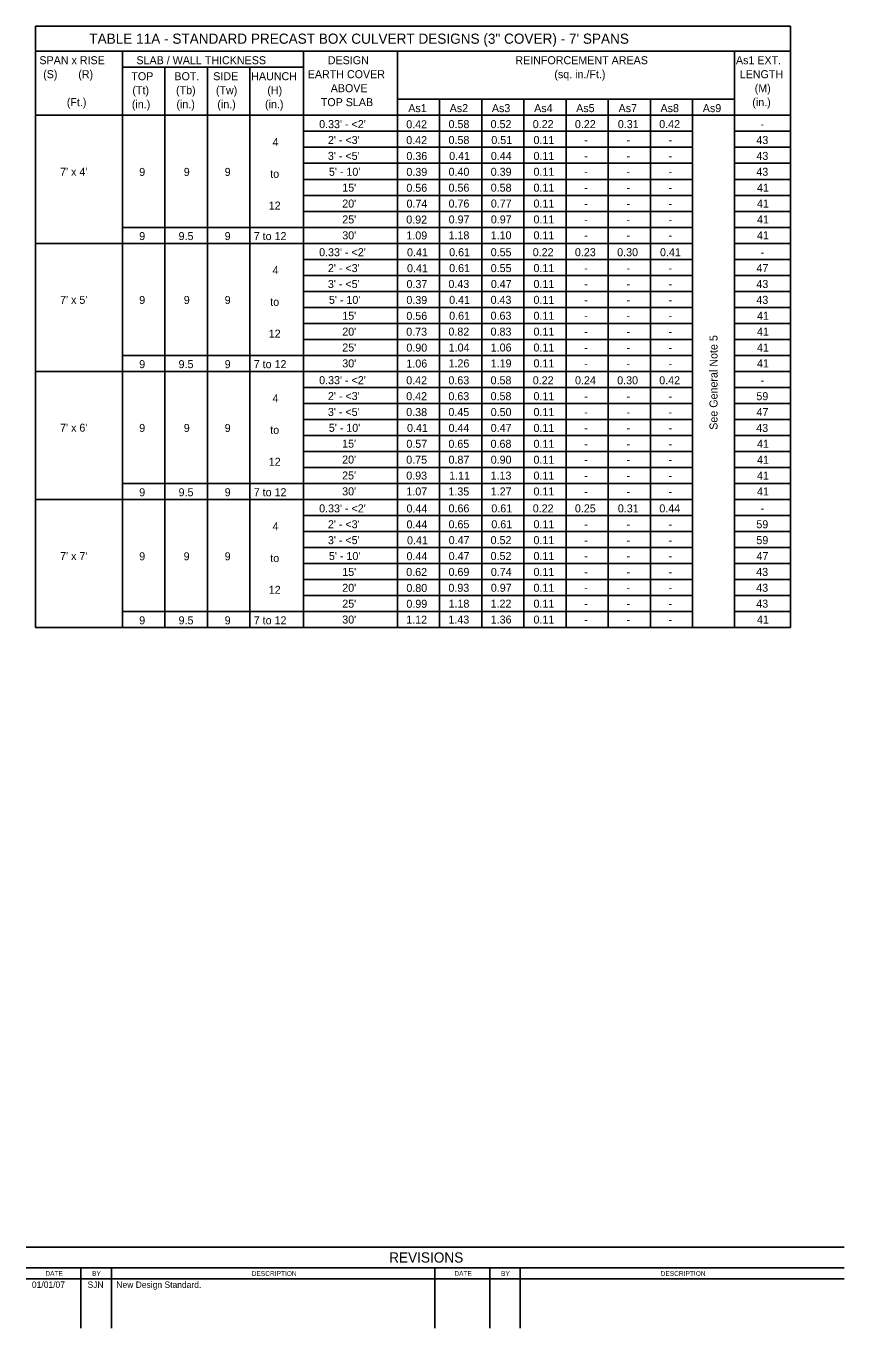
# Model space of a CAD drawing. Extents: x 10342.77 to 10344.98, y 76371.51 to 76372.62.
# Drawn here: x 10342.77 to 10343.414, y 76371.51 to 76372.535 of the extents above; entities that cross this region are included whole.
import ezdxf

# ---------------------------------------------------------------- set-up
doc = ezdxf.new("R2010")
doc.units = 0
for name, color, linetype in [('AdhocPoint_dp', 7, 'Continuous'), ('Border', 7, 'Continuous'), ('PlotBorder_dp', 7, 'Continuous')]:
    doc.layers.add(name, color=color, linetype=linetype)

msp = doc.modelspace()

# ---------------------------------------------------------------- linework, layer by layer
at = {"layer": 'Border'}
for p, q in [((10343.4138, 76371.5736), (10342.7697, 76371.5736)), ((10343.4138, 76371.5575), (10342.7697, 76371.5575)), ((10342.8127, 76371.5575), (10342.8127, 76371.5101)), ((10342.8369, 76371.5575), (10342.8369, 76371.5101)), ((10343.0917, 76371.5575), (10343.0917, 76371.5101)), ((10343.1348, 76371.5575), (10343.1348, 76371.5101)), ((10343.1589, 76371.5575), (10343.1589, 76371.5101)), ((10342.7697, 76371.5489), (10343.4138, 76371.5489))]:
    msp.add_line(p, q, dxfattribs=at)
at = {"layer": 'PlotBorder_dp'}
for p, q in [((10342.7771, 76372.5347), (10343.3718, 76372.5347)), ((10342.7771, 76372.5347), (10342.7771, 76372.0613)), ((10343.3718, 76372.5347), (10343.3718, 76372.0613)), ((10342.7771, 76372.5149), (10343.3718, 76372.5149)), ((10342.8457, 76372.5149), (10342.8457, 76372.0613)), ((10342.9882, 76372.5149), (10342.9882, 76372.0613)), ((10343.0621, 76372.5149), (10343.0621, 76372.0613)), ((10343.3277, 76372.5149), (10343.3277, 76372.0613)), ((10342.8457, 76372.5023), (10342.9882, 76372.5023)), ((10342.8791, 76372.5023), (10342.8791, 76372.0613)), ((10342.9125, 76372.5023), (10342.9125, 76372.0613)), ((10342.9458, 76372.5023), (10342.9458, 76372.0613)), ((10343.0621, 76372.4771), (10343.3277, 76372.4771)), ((10343.0953, 76372.4771), (10343.0953, 76372.0613)), ((10343.1285, 76372.4771), (10343.1285, 76372.0613)), ((10343.1617, 76372.4771), (10343.1617, 76372.0613)), ((10343.1949, 76372.4771), (10343.1949, 76372.0613)), ((10343.2281, 76372.4771), (10343.2281, 76372.0613)), ((10343.2281, 76372.4771), (10343.2281, 76372.0613)), ((10343.2613, 76372.4771), (10343.2613, 76372.0613)), ((10343.2945, 76372.4771), (10343.2945, 76372.0613)), ((10342.7771, 76372.4645), (10343.3718, 76372.4645)), ((10342.9882, 76372.4519), (10343.2945, 76372.4519)), ((10343.3277, 76372.4519), (10343.3718, 76372.4519)), ((10342.9882, 76372.4393), (10343.2945, 76372.4393)), ((10343.3277, 76372.4393), (10343.3718, 76372.4393)), ((10342.9882, 76372.4267), (10343.2945, 76372.4267)), ((10343.3277, 76372.4267), (10343.3718, 76372.4267)), ((10342.9882, 76372.4141), (10343.2945, 76372.4141)), ((10343.3277, 76372.4141), (10343.3718, 76372.4141)), ((10342.9882, 76372.4015), (10343.2945, 76372.4015)), ((10343.3277, 76372.4015), (10343.3718, 76372.4015)), ((10342.9882, 76372.3889), (10343.2945, 76372.3889)), ((10343.3277, 76372.3889), (10343.3718, 76372.3889)), ((10342.9882, 76372.3763), (10342.8457, 76372.3763)), ((10342.9882, 76372.3763), (10343.2945, 76372.3763)), ((10343.3277, 76372.3763), (10343.3718, 76372.3763)), ((10342.7771, 76372.3637), (10343.2945, 76372.3637)), ((10342.9888, 76372.3637), (10343.061, 76372.3637)), ((10343.3277, 76372.3637), (10343.3718, 76372.3637)), ((10342.9882, 76372.3511), (10343.2945, 76372.3511)), ((10343.3277, 76372.3511), (10343.3718, 76372.3511)), ((10342.9882, 76372.3385), (10343.2945, 76372.3385)), ((10343.3277, 76372.3385), (10343.3718, 76372.3385)), ((10342.9882, 76372.3259), (10343.2945, 76372.3259)), ((10343.3277, 76372.3259), (10343.3718, 76372.3259)), ((10342.9882, 76372.3133), (10343.2945, 76372.3133)), ((10343.3277, 76372.3133), (10343.3718, 76372.3133)), ((10342.9882, 76372.3007), (10343.2945, 76372.3007)), ((10343.3277, 76372.3007), (10343.3718, 76372.3007)), ((10342.9882, 76372.2881), (10343.2945, 76372.2881)), ((10343.3277, 76372.2881), (10343.3718, 76372.2881)), ((10342.9888, 76372.2755), (10342.8457, 76372.2755)), ((10342.9882, 76372.2755), (10343.2945, 76372.2755)), ((10342.9888, 76372.2755), (10343.061, 76372.2755)), ((10343.3277, 76372.2755), (10343.3718, 76372.2755)), ((10342.7771, 76372.2629), (10343.2945, 76372.2629)), ((10343.3277, 76372.2629), (10343.3718, 76372.2629)), ((10342.9882, 76372.2503), (10343.2945, 76372.2503)), ((10343.3277, 76372.2503), (10343.3718, 76372.2503)), ((10342.9882, 76372.2377), (10343.2945, 76372.2377)), ((10343.3277, 76372.2377), (10343.3718, 76372.2377)), ((10342.9882, 76372.2251), (10343.2945, 76372.2251)), ((10343.3277, 76372.2251), (10343.3718, 76372.2251)), ((10342.9882, 76372.2125), (10343.2945, 76372.2125)), ((10343.3277, 76372.2125), (10343.3718, 76372.2125)), ((10342.9882, 76372.1999), (10343.2945, 76372.1999)), ((10343.3277, 76372.1999), (10343.3718, 76372.1999)), ((10342.9882, 76372.1873), (10343.2945, 76372.1873)), ((10343.3277, 76372.1873), (10343.3718, 76372.1873)), ((10342.9882, 76372.1747), (10342.8457, 76372.1747)), ((10342.9882, 76372.1747), (10343.2945, 76372.1747)), ((10343.3277, 76372.1747), (10343.3718, 76372.1747)), ((10342.7771, 76372.1621), (10343.2945, 76372.1621)), ((10343.3277, 76372.1621), (10343.3718, 76372.1621)), ((10342.9882, 76372.1495), (10343.2945, 76372.1495)), ((10343.3277, 76372.1495), (10343.3718, 76372.1495)), ((10342.9882, 76372.1369), (10343.2945, 76372.1369)), ((10343.3277, 76372.1369), (10343.3718, 76372.1369)), ((10342.9882, 76372.1243), (10343.2945, 76372.1243)), ((10343.3277, 76372.1243), (10343.3718, 76372.1243)), ((10342.9882, 76372.1117), (10343.2945, 76372.1117)), ((10343.3277, 76372.1117), (10343.3718, 76372.1117)), ((10342.9882, 76372.0991), (10343.2945, 76372.0991)), ((10343.3277, 76372.0991), (10343.3718, 76372.0991)), ((10342.9882, 76372.0865), (10343.2945, 76372.0865)), ((10343.3277, 76372.0865), (10343.3718, 76372.0865)), ((10342.9882, 76372.0739), (10342.8457, 76372.0739)), ((10342.9882, 76372.0739), (10343.2945, 76372.0739)), ((10343.3277, 76372.0739), (10343.3718, 76372.0739)), ((10342.7771, 76372.0613), (10343.3718, 76372.0613)), ((10342.9888, 76372.0613), (10343.061, 76372.0613))]:
    msp.add_line(p, q, dxfattribs=at)

# ---------------------------------------------------------------- texts
at = {"layer": 'AdhocPoint_dp'}
for s, height, p in [('TABLE 11A - STANDARD PRECAST BOX CULVERT DESIGNS (3" COVER) - 7\' SPANS', 0.008, (10342.8195, 76372.5208)), ('SLAB / WALL THICKNESS', 0.0063, (10342.8566, 76372.5047)), ('As1', 0.0063, (10343.0707, 76372.467)), ('As2', 0.0063, (10343.1033, 76372.467)), ('As3', 0.0063, (10343.1365, 76372.467)), ('As4', 0.0063, (10343.1698, 76372.467)), ('As5', 0.0063, (10343.2029, 76372.467)), ('As7', 0.0063, (10343.2363, 76372.467)), ('As8', 0.0063, (10343.2693, 76372.467)), ('As9', 0.0063, (10343.3026, 76372.467)), ('9', 0.0063, (10342.8588, 76372.4168)), ('9', 0.0063, (10342.8939, 76372.4168)), ('9', 0.0063, (10342.9261, 76372.4168)), ('9', 0.0063, (10342.8588, 76372.3663)), ('9.5', 0.0063, (10342.8898, 76372.3663)), ('9', 0.0063, (10342.9261, 76372.3663)), ('7 to 12', 0.0063, (10342.949, 76372.3663)), ('9', 0.0063, (10342.8588, 76372.316)), ('9', 0.0063, (10342.8939, 76372.316)), ('9', 0.0063, (10342.9261, 76372.316)), ('9', 0.0063, (10342.8588, 76372.2655)), ('9.5', 0.0063, (10342.8898, 76372.2655)), ('9', 0.0063, (10342.9261, 76372.2655)), ('7 to 12', 0.0063, (10342.949, 76372.2655)), ('9', 0.0063, (10342.8588, 76372.2153)), ('9', 0.0063, (10342.8939, 76372.2153)), ('9', 0.0063, (10342.9261, 76372.2153)), ('9', 0.0063, (10342.8588, 76372.1647)), ('9.5', 0.0063, (10342.8898, 76372.1647)), ('9', 0.0063, (10342.9261, 76372.1647)), ('7 to 12', 0.0063, (10342.949, 76372.1647)), ('9', 0.0063, (10342.8588, 76372.1143)), ('9', 0.0063, (10342.8938, 76372.1143)), ('9', 0.0063, (10342.9261, 76372.1143)), ('9', 0.0063, (10342.8588, 76372.0639)), ('9.5', 0.0063, (10342.8898, 76372.0639)), ('9', 0.0063, (10342.9261, 76372.0639)), ('7 to 12', 0.0063, (10342.949, 76372.0639)), ('REVISIONS', 0.00802, (10343.0556, 76371.5616)), ('01/01/07', 0.005, (10342.7743, 76371.5417)), ('SJN', 0.005, (10342.8181, 76371.5417)), ('BY', 0.00375, (10342.8217, 76371.5511)), ('New Design Standard.', 0.005, (10342.8408, 76371.5417)), ('BY', 0.00375, (10343.1437, 76371.5511))]:
    msp.add_text(s, height=height, dxfattribs=at).set_placement(p)
for s, height, rotation, p in [('See General Note 5', 0.0063, 90, (10343.3142, 76372.217)), ('DATE', 0.00374, 359.8693, (10342.7849, 76371.5512)), ('DESCRIPTION', 0.003752, 0.0498, (10342.9474, 76371.5511)), ('DATE', 0.00374, 359.8693, (10343.107, 76371.5512)), ('DESCRIPTION', 0.003752, 0.0498, (10343.2694, 76371.5511))]:
    msp.add_text(s, height=height, rotation=rotation, dxfattribs=at).set_placement(p)
at = {"layer": 'PlotBorder_dp'}
for s, p in [('SPAN x RISE', (10342.7802, 76372.5047)), ('DESIGN', (10343.0073, 76372.5047)), ('REINFORCEMENT AREAS', (10343.155, 76372.5047)), ('(S)       (R)', (10342.7832, 76372.4937)), ('TOP', (10342.8526, 76372.4921)), ('BOT.', (10342.8865, 76372.4921)), ('SIDE', (10342.9171, 76372.4921)), ('HAUNCH', (10342.947, 76372.4921)), ('EARTH COVER', (10342.9915, 76372.4937)), ('(sq. in./Ft.)', (10343.1857, 76372.4937)), ('(Tt)', (10342.8534, 76372.4811)), ('(Tb)', (10342.8878, 76372.4811)), ('(Tw)', (10342.9192, 76372.4811)), ('(H)', (10342.9597, 76372.4811)), ('ABOVE', (10343.0096, 76372.4827)), ('(Ft.)', (10342.8018, 76372.4717)), ('TOP SLAB', (10343.0018, 76372.4717)), ('(in.)', (10342.853, 76372.4701)), ('(in.)', (10342.8881, 76372.4701)), ('(in.)', (10342.9203, 76372.4701)), ('(in.)', (10342.9579, 76372.4701)), ("0.33' - <2'", (10343.0005, 76372.4544)), ('0.42', (10343.0691, 76372.4543)), ('0.58', (10343.1024, 76372.4544)), ('0.52', (10343.1355, 76372.4544)), ('0.22', (10343.1687, 76372.4544)), ('0.22', (10343.2019, 76372.4544)), ('0.31', (10343.2357, 76372.4544)), ('0.42', (10343.2683, 76372.4544)), ('-', (10343.3481, 76372.4544)), ('4', (10342.9638, 76372.4403)), ("2' - <3'", (10343.0074, 76372.4419)), ('0.42', (10343.0691, 76372.4418)), ('0.58', (10343.1024, 76372.4419)), ('0.51', (10343.1361, 76372.4419)), ('0.11', (10343.1693, 76372.4419)), ('43', (10343.3448, 76372.4419)), ('-', (10343.2093, 76372.4419)), ('-', (10343.2425, 76372.4419)), ('-', (10343.2757, 76372.4419)), ("3' - <5'", (10343.0074, 76372.4294)), ('0.36', (10343.0692, 76372.4293)), ('0.41', (10343.1029, 76372.4294)), ('0.44', (10343.1357, 76372.4294)), ('0.11', (10343.1693, 76372.4294)), ('-', (10343.2093, 76372.4294)), ('-', (10343.2425, 76372.4294)), ('-', (10343.2757, 76372.4294)), ('43', (10343.3448, 76372.4294)), ("7' x 4'", (10342.7965, 76372.4169)), ('to', (10342.962, 76372.4153)), ("5' - 10'", (10343.0082, 76372.4169)), ('0.39', (10343.0692, 76372.4168)), ('0.40', (10343.1024, 76372.4169)), ('0.39', (10343.1356, 76372.4169)), ('0.11', (10343.1693, 76372.4169)), ('-', (10343.2093, 76372.4169)), ('-', (10343.2425, 76372.4169)), ('-', (10343.2757, 76372.4169)), ('43', (10343.3448, 76372.4169)), ("15'", (10343.0187, 76372.4044)), ('0.56', (10343.0692, 76372.4043)), ('0.56', (10343.1024, 76372.4044)), ('0.58', (10343.1356, 76372.4044)), ('0.11', (10343.1693, 76372.4044)), ('-', (10343.2093, 76372.4044)), ('-', (10343.2425, 76372.4044)), ('-', (10343.2757, 76372.4044)), ('41', (10343.3453, 76372.4044)), ('12', (10342.9608, 76372.3903)), ("20'", (10343.0187, 76372.3919)), ('0.74', (10343.0693, 76372.3918)), ('0.76', (10343.1024, 76372.3919)), ('0.77', (10343.1357, 76372.3919)), ('0.11', (10343.1693, 76372.3919)), ('41', (10343.3453, 76372.3919)), ("25'", (10343.0187, 76372.3794)), ('0.92', (10343.0691, 76372.3793)), ('0.97', (10343.1025, 76372.3794)), ('0.97', (10343.1357, 76372.3794)), ('0.11', (10343.1693, 76372.3794)), ('-', (10343.2093, 76372.3919)), ('-', (10343.2425, 76372.3919)), ('-', (10343.2757, 76372.3919)), ('41', (10343.3453, 76372.3794)), ('-', (10343.2093, 76372.3794)), ('-', (10343.2425, 76372.3794)), ('-', (10343.2757, 76372.3794)), ("30'", (10343.0187, 76372.3669)), ('1.09', (10343.0692, 76372.3668)), ('1.18', (10343.1024, 76372.3669)), ('1.10', (10343.1356, 76372.3669)), ('0.11', (10343.1693, 76372.3669)), ('-', (10343.2093, 76372.3669)), ('-', (10343.2425, 76372.3669)), ('-', (10343.2757, 76372.3669)), ('41', (10343.3453, 76372.3669)), ("0.33' - <2'", (10343.0005, 76372.3536)), ('0.41', (10343.0697, 76372.3535)), ('0.61', (10343.1029, 76372.3536)), ('0.55', (10343.1356, 76372.3536)), ('0.22', (10343.1687, 76372.3536)), ('0.23', (10343.2019, 76372.3536)), ('0.30', (10343.2352, 76372.3536)), ('0.41', (10343.2689, 76372.3536)), ('-', (10343.3481, 76372.3536)), ('4', (10342.9638, 76372.3395)), ("2' - <3'", (10343.0074, 76372.3411)), ('0.41', (10343.0697, 76372.341)), ('0.61', (10343.1029, 76372.3411)), ('0.55', (10343.1356, 76372.3411)), ('0.11', (10343.1693, 76372.3411)), ('-', (10343.2093, 76372.3411)), ('-', (10343.2425, 76372.3411)), ('-', (10343.2757, 76372.3411)), ('47', (10343.3449, 76372.3411)), ("3' - <5'", (10343.0074, 76372.3286)), ('0.37', (10343.0693, 76372.3285)), ('0.43', (10343.1023, 76372.3286)), ('0.47', (10343.1357, 76372.3286)), ('0.11', (10343.1693, 76372.3286)), ('43', (10343.3448, 76372.3286)), ('-', (10343.2093, 76372.3286)), ('-', (10343.2425, 76372.3286)), ('-', (10343.2757, 76372.3286)), ("7' x 5'", (10342.7965, 76372.3161)), ('to', (10342.962, 76372.3145)), ("5' - 10'", (10343.0082, 76372.3161)), ('0.39', (10343.0692, 76372.316)), ('0.41', (10343.1029, 76372.3161)), ('0.43', (10343.1355, 76372.3161)), ('0.11', (10343.1693, 76372.3161)), ('-', (10343.2093, 76372.3161)), ('-', (10343.2425, 76372.3161)), ('-', (10343.2757, 76372.3161)), ('43', (10343.3448, 76372.3161)), ("15'", (10343.0187, 76372.3036)), ('0.56', (10343.0692, 76372.3035)), ('0.61', (10343.1029, 76372.3036)), ('0.63', (10343.1355, 76372.3036)), ('0.11', (10343.1693, 76372.3036)), ('-', (10343.2093, 76372.3036)), ('-', (10343.2425, 76372.3036)), ('-', (10343.2757, 76372.3036)), ('41', (10343.3453, 76372.3036)), ('12', (10342.9608, 76372.2895)), ("20'", (10343.0187, 76372.2911)), ('0.73', (10343.0691, 76372.291)), ('0.82', (10343.1023, 76372.2911)), ('0.83', (10343.1355, 76372.2911)), ('0.11', (10343.1693, 76372.2911)), ('-', (10343.2093, 76372.2911)), ('-', (10343.2425, 76372.2911)), ('-', (10343.2757, 76372.2911)), ('41', (10343.3453, 76372.2911)), ("25'", (10343.0187, 76372.2786)), ('0.90', (10343.0692, 76372.2785)), ('1.04', (10343.1025, 76372.2786)), ('1.06', (10343.1356, 76372.2786)), ('0.11', (10343.1693, 76372.2786)), ('41', (10343.3453, 76372.2786)), ("30'", (10343.0187, 76372.2661)), ('1.06', (10343.0692, 76372.266)), ('1.26', (10343.1024, 76372.2661)), ('1.19', (10343.1356, 76372.2661)), ('0.11', (10343.1693, 76372.2661)), ('-', (10343.2093, 76372.2786)), ('-', (10343.2425, 76372.2786)), ('-', (10343.2757, 76372.2786)), ('41', (10343.3453, 76372.2661)), ('-', (10343.2093, 76372.2661)), ('-', (10343.2425, 76372.2661)), ('-', (10343.2757, 76372.2661)), ("0.33' - <2'", (10343.0005, 76372.2529)), ('0.42', (10343.0691, 76372.2528)), ('0.63', (10343.1023, 76372.2528)), ('0.58', (10343.1355, 76372.2528)), ('0.22', (10343.1687, 76372.2528)), ('0.24', (10343.202, 76372.2528)), ('0.30', (10343.2352, 76372.2528)), ('0.42', (10343.2683, 76372.2528)), ('-', (10343.3481, 76372.2528)), ('4', (10342.9638, 76372.2387)), ("2' - <3'", (10343.0074, 76372.2404)), ('0.42', (10343.0691, 76372.2403)), ('0.63', (10343.1023, 76372.2403)), ('0.58', (10343.1355, 76372.2403)), ('0.11', (10343.1693, 76372.2403)), ('- ', (10343.2093, 76372.2403)), ('-', (10343.2425, 76372.2403)), ('-', (10343.2757, 76372.2403)), ('59', (10343.3448, 76372.2403)), ("3' - <5'", (10343.0074, 76372.2279)), ('0.38', (10343.0691, 76372.2278)), ('0.45', (10343.1023, 76372.2278)), ('0.50', (10343.1356, 76372.2278)), ('0.11', (10343.1693, 76372.2278)), ('47', (10343.3449, 76372.2278)), ("7' x 6'", (10342.7965, 76372.2155)), ("5' - 10'", (10343.0081, 76372.2154)), ('0.41', (10343.0697, 76372.2153)), ('0.44', (10343.1024, 76372.2153)), ('0.47', (10343.1356, 76372.2153)), ('0.11', (10343.1693, 76372.2153)), ('-', (10343.2093, 76372.2278)), ('-', (10343.2425, 76372.2278)), ('-', (10343.2757, 76372.2278)), ('43', (10343.3447, 76372.2153)), ('to', (10342.962, 76372.2137)), ('-', (10343.2093, 76372.2153)), ('-', (10343.2425, 76372.2153)), ('-', (10343.2757, 76372.2153)), ("15'", (10343.0186, 76372.2029)), ('0.57', (10343.0692, 76372.2028)), ('0.65', (10343.1023, 76372.2028)), ('0.68', (10343.1355, 76372.2028)), ('0.11', (10343.1693, 76372.2028)), ('-', (10343.2093, 76372.2028)), ('-', (10343.2425, 76372.2028)), ('-', (10343.2757, 76372.2028)), ('41', (10343.3453, 76372.2028)), ('12', (10342.9608, 76372.1887)), ("20'", (10343.0186, 76372.1904)), ('0.75', (10343.0691, 76372.1903)), ('0.87', (10343.1024, 76372.1903)), ('0.90', (10343.1356, 76372.1903)), ('0.11', (10343.1693, 76372.1903)), ('-', (10343.2093, 76372.1903)), ('-', (10343.2425, 76372.1903)), ('-', (10343.2757, 76372.1903)), ('41', (10343.3453, 76372.1903)), ("25'", (10343.0186, 76372.1779)), ('0.93', (10343.0691, 76372.1778)), ('1.11', (10343.1029, 76372.1778)), ('1.13', (10343.1355, 76372.1778)), ('0.11', (10343.1693, 76372.1778)), ('-', (10343.2093, 76372.1778)), ('-', (10343.2425, 76372.1778)), ('-', (10343.2757, 76372.1778)), ('41', (10343.3453, 76372.1778)), ("30'", (10343.0186, 76372.1654)), ('1.07', (10343.0692, 76372.1653)), ('1.35', (10343.1023, 76372.1653)), ('1.27', (10343.1356, 76372.1653)), ('0.11', (10343.1693, 76372.1653)), ('41', (10343.3453, 76372.1653)), ('-', (10343.2093, 76372.1653)), ('-', (10343.2425, 76372.1653)), ('-', (10343.2757, 76372.1653)), ("0.33' - <2'", (10343.0005, 76372.152)), ('0.44', (10343.0693, 76372.1519)), ('0.66', (10343.1024, 76372.152)), ('0.61', (10343.1361, 76372.152)), ('0.22', (10343.1687, 76372.152)), ('0.25', (10343.2019, 76372.152)), ('0.31', (10343.2357, 76372.152)), ('0.44', (10343.2684, 76372.152)), ('-', (10343.3481, 76372.152)), ('4', (10342.9638, 76372.1379)), ("2' - <3'", (10343.0074, 76372.1395)), ('0.44', (10343.0693, 76372.1394)), ('0.65', (10343.1024, 76372.1395)), ('0.61', (10343.1361, 76372.1395)), ('0.11', (10343.1693, 76372.1395)), ('- ', (10343.2093, 76372.1395)), ('-', (10343.2425, 76372.1395)), ('-', (10343.2757, 76372.1395)), ('59', (10343.3448, 76372.1395)), ("3' - <5'", (10343.0074, 76372.127)), ('0.41', (10343.0697, 76372.1269)), ('0.47', (10343.1025, 76372.127)), ('0.52', (10343.1355, 76372.127)), ('0.11', (10343.1693, 76372.127)), ('-', (10343.2093, 76372.127)), ('-', (10343.2425, 76372.127)), ('-', (10343.2757, 76372.127)), ('59', (10343.3448, 76372.127)), ("7' x 7'", (10342.7965, 76372.1145)), ('to', (10342.962, 76372.1129)), ("5' - 10'", (10343.0082, 76372.1145)), ('0.44', (10343.0693, 76372.1144)), ('0.47', (10343.1025, 76372.1145)), ('0.52', (10343.1355, 76372.1145)), ('0.11', (10343.1693, 76372.1145)), ('47', (10343.3449, 76372.1145)), ("15'", (10343.0187, 76372.102)), ('0.62', (10343.0691, 76372.1019)), ('0.69', (10343.1024, 76372.102)), ('0.74', (10343.1357, 76372.102)), ('0.11', (10343.1693, 76372.102)), ('-', (10343.2093, 76372.1145)), ('-', (10343.2425, 76372.1145)), ('-', (10343.2757, 76372.1145)), ('43', (10343.3447, 76372.102)), ('-', (10343.2093, 76372.102)), ('-', (10343.2425, 76372.102)), ('-', (10343.2757, 76372.102)), ('12', (10342.9608, 76372.0879)), ("20'", (10343.0187, 76372.0895)), ('0.80', (10343.0692, 76372.0894)), ('0.93', (10343.1023, 76372.0895)), ('0.97', (10343.1357, 76372.0895)), ('0.11', (10343.1693, 76372.0895)), ('-', (10343.2093, 76372.0895)), ('-', (10343.2425, 76372.0895)), ('-', (10343.2757, 76372.0895)), ('43', (10343.3447, 76372.0895)), ("25'", (10343.0187, 76372.077)), ('0.99', (10343.0692, 76372.0769)), ('1.18', (10343.1024, 76372.077)), ('1.22', (10343.1355, 76372.077)), ('0.11', (10343.1693, 76372.077)), ('-', (10343.2093, 76372.077)), ('-', (10343.2425, 76372.077)), ('-', (10343.2757, 76372.077)), ('43', (10343.3447, 76372.077)), ("30'", (10343.0187, 76372.0645)), ('1.12', (10343.0691, 76372.0644)), ('1.43', (10343.1023, 76372.0645)), ('1.36', (10343.1356, 76372.0645)), ('0.11', (10343.1693, 76372.0645)), ('-', (10343.2093, 76372.0645)), ('-', (10343.2425, 76372.0645)), ('-', (10343.2757, 76372.0645)), ('41', (10343.3453, 76372.0645))]:
    msp.add_text(s, height=0.0063, dxfattribs=at).set_placement(p)
for s, p in [('As1 EXT.', (10343.3287, 76372.5047)), ('LENGTH', (10343.3317, 76372.4937)), ('(M)', (10343.3435, 76372.4827)), ('(in.)', (10343.3416, 76372.4717))]:
    msp.add_text(s, height=0.0063, rotation=360, dxfattribs=at).set_placement(p)

doc.saveas('drawing.dxf')
